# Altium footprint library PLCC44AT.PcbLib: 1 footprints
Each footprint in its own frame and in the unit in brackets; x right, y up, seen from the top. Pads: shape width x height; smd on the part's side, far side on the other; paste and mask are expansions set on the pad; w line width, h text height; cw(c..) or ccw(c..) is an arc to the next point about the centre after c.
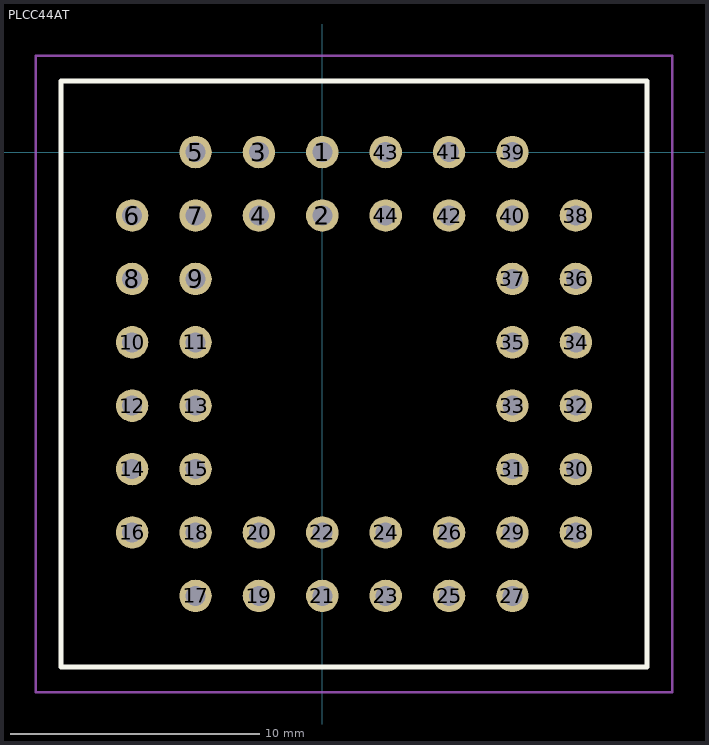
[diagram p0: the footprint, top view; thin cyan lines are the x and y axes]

## PLCC44AT [mm]
pads (44):
  round 1.3 hole 0.8: 1(0,0) 2(0,-2.54) 3(-2.54,0) 4(-2.54,-2.54) 5(-5.08,0) 6(-7.62,-2.54) 7(-5.08,-2.54) 8(-7.62,-5.08) 9(-5.08,-5.08) 10(-7.62,-7.62) 11(-5.08,-7.62) 12(-7.62,-10.16) 13(-5.08,-10.16) 14(-7.62,-12.7) 15(-5.08,-12.7) 16(-7.62,-15.24) 17(-5.08,-17.78) 18(-5.08,-15.24) 19(-2.54,-17.78) 20(-2.54,-15.24) 21(0,-17.78) 22(0,-15.24) 23(2.54,-17.78) 24(2.54,-15.24) 25(5.08,-17.78) 26(5.08,-15.24) 27(7.62,-17.78) 28(10.16,-15.24) 29(7.62,-15.24) 30(10.16,-12.7) 31(7.62,-12.7) 32(10.16,-10.16) 33(7.62,-10.16) 34(10.16,-7.62) 35(7.62,-7.62) 36(10.16,-5.08) 37(7.62,-5.08) 38(10.16,-2.54) 39(7.62,0) 40(7.62,-2.54) 41(5.08,0) 42(5.08,-2.54) 43(2.54,0) 44(2.54,-2.54)
Top Overlay:
  lines w0.2: -10.48,-20.64 13.02,-20.64 13.02,2.86 -10.48,2.86 -10.48,-20.64
Mechanical 15:
  lines w0.1: -10.48,-20.64 13.02,-20.64 13.02,2.86 -10.48,2.86 -10.48,-20.64
Mechanical 20:
  lines w0.1: -11.48,-21.64 14.02,-21.64 14.02,3.86 -11.48,3.86 -11.48,-21.64
3D body "PLCC-44-AT.stp": height 5.8, standoff -4.65, extent -10,-3.376 10,3.376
